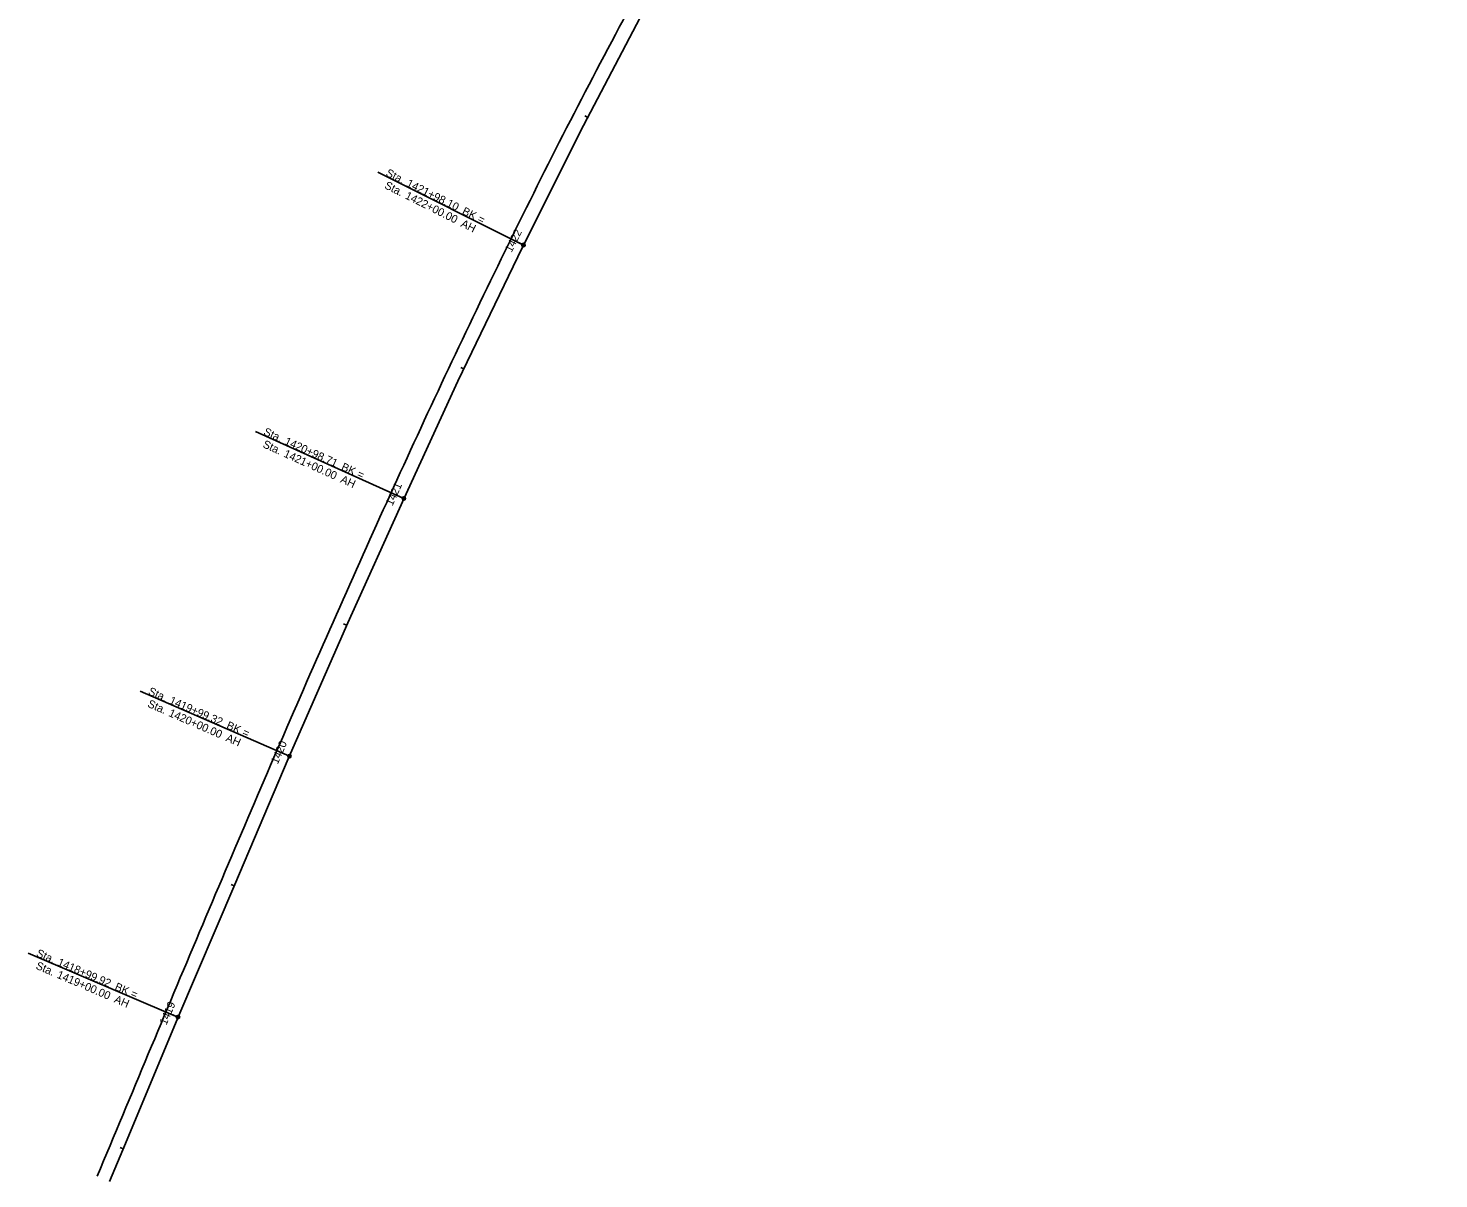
# Model space of a CAD drawing. Extents: x 158351 to 160372, y 373672 to 375743.
# Drawn here: x 158581.7 to 159075.4, y 374197.4 to 374600.1 of the extents above; entities that cross this region are included whole.
import ezdxf

# ---------------------------------------------------------------- set-up
doc = ezdxf.new("R2010")
doc.units = 0
for name, color, linetype in [('Default', 7, 'Continuous'), ('GE_X_Alignment', 7, 'Continuous'), ('GE_X_Alignment_1000_Cardinal_Points', 7, 'Continuous'), ('GE_X_Alignment_1000_Stations', 7, 'Continuous'), ('GE_X_Alignment_100_Cardinal_Points', 7, 'Continuous'), ('GE_X_Alignment_100_Stations', 7, 'Continuous'), ('GE_X_Alignment_500_Cardinal_Points', 7, 'Continuous'), ('GE_X_Alignment_500_Stations', 7, 'Continuous')]:
    doc.layers.add(name, color=color, linetype=linetype)

msp = doc.modelspace()

# ---------------------------------------------------------------- linework, layer by layer
at = {"layer": 'Default'}
msp.add_open_spline([(158605.87, 374198.29), (158611.83, 374212.58), (158623.73, 374241.11), (158641.65, 374283.82), (158659.69, 374326.35), (158677.95, 374368.65), (158696.5, 374410.69), (158715.42, 374452.44), (158734.8, 374493.84), (158754.72, 374534.84), (158775.19, 374575.44), (158789.46, 374602.13), (158796.59, 374615.46)], degree=3, dxfattribs=at)
at = {"layer": 'GE_X_Alignment'}
msp.add_lwpolyline([(158610.16, 374196.5), (158615.74, 374209.73), (158634.02, 374253.79), (158653.96, 374300.37), (158672.72, 374344.4), (158693.52, 374392.04), (158713.24, 374435.64), (158732.12, 374476.57), (158754.66, 374523.45), (158776.04, 374566.09), (158799.53, 374610.86), (158824.66, 374655.89), (158846.86, 374694.4), (158871.75, 374734.35), (158899.56, 374777.58), (158924.58, 374814.76), (158954.14, 374857.23), (158981.31, 374893.58), (159012.91, 374934.64), (159042.19, 374970.87), (159075.38, 375009.78)], dxfattribs=at)
at = {"layer": 'GE_X_Alignment_1000_Cardinal_Points'}
for p, q in [((158755.06, 374524.24), (158704.1, 374549.79)), ((158713.19, 374435.53), (158661.25, 374459.02)), ((158673.13, 374345.32), (158620.88, 374368.12)), ((158634.11, 374253.99), (158581.7, 374276.41))]:
    msp.add_line(p, q, dxfattribs=at)
for centre in [(158755.06, 374524.24), (158713.19, 374435.53), (158673.13, 374345.32), (158634.11, 374253.99)]:
    msp.add_circle(centre, 0.6, dxfattribs=at)
at = {"layer": 'GE_X_Alignment_1000_Stations'}
msp.add_line((158673.13, 374345.32), (158671.29, 374346.12), dxfattribs=at)
at = {"layer": 'GE_X_Alignment_100_Cardinal_Points'}
for p, q in [((158755.06, 374524.24), (158704.1, 374549.79)), ((158713.19, 374435.53), (158661.25, 374459.02)), ((158673.13, 374345.32), (158620.88, 374368.12)), ((158634.11, 374253.99), (158581.7, 374276.41))]:
    msp.add_line(p, q, dxfattribs=at)
for centre in [(158755.06, 374524.24), (158713.19, 374435.53), (158673.13, 374345.32), (158634.11, 374253.99)]:
    msp.add_circle(centre, 0.6, dxfattribs=at)
at = {"layer": 'GE_X_Alignment_100_Stations'}
for p, q in [((158777.52, 374568.91), (158776.46, 374569.47)), ((158755.06, 374524.24), (158753.27, 374525.14)), ((158734.2, 374480.9), (158733.12, 374481.42)), ((158713.19, 374435.53), (158711.36, 374436.35)), ((158693.12, 374391.14), (158692.02, 374391.62)), ((158673.13, 374345.32), (158671.29, 374346.12)), ((158653.78, 374299.95), (158652.68, 374300.43)), ((158634.11, 374253.99), (158632.27, 374254.77)), ((158614.97, 374207.89), (158613.86, 374208.35))]:
    msp.add_line(p, q, dxfattribs=at)
at = {"layer": 'GE_X_Alignment_500_Cardinal_Points'}
for p, q in [((158755.06, 374524.24), (158704.1, 374549.79)), ((158713.19, 374435.53), (158661.25, 374459.02)), ((158673.13, 374345.32), (158620.88, 374368.12)), ((158634.11, 374253.99), (158581.7, 374276.41))]:
    msp.add_line(p, q, dxfattribs=at)
for centre in [(158755.06, 374524.24), (158713.19, 374435.53), (158673.13, 374345.32), (158634.11, 374253.99)]:
    msp.add_circle(centre, 0.6, dxfattribs=at)
at = {"layer": 'GE_X_Alignment_500_Stations'}
for p, q in [((158755.06, 374524.24), (158753.98, 374524.78)), ((158713.19, 374435.53), (158712.09, 374436.02)), ((158673.13, 374345.32), (158671.29, 374346.12)), ((158634.11, 374253.99), (158633, 374254.46))]:
    msp.add_line(p, q, dxfattribs=at)

# ---------------------------------------------------------------- texts
at = {"layer": 'GE_X_Alignment_1000_Cardinal_Points'}
for s, rotation, p in [('Sta. ', 333.3717, (158706.62, 374548.57)), ('Sta. ', 333.3717, (158706.16, 374544.22)), ('1421+98.10', 333.3717, (158713.81, 374544.97)), ('1422+00.00', 333.3717, (158713.36, 374540.62)), (' BK =', 333.3717, (158732.38, 374535.66)), (' AH', 333.3717, (158731.92, 374531.31)), ('Sta. ', 335.6619, (158663.82, 374457.91)), ('Sta. ', 335.6619, (158663.54, 374453.54)), ('1420+98.71', 335.6619, (158671.15, 374454.59)), ('1421+00.00', 335.6619, (158670.86, 374450.23)), (' BK =', 335.6619, (158690.07, 374446.04)), (' AH', 335.6619, (158689.79, 374441.67)), ('Sta. ', 336.4232, (158623.47, 374367.04)), ('Sta. ', 336.4232, (158623.24, 374362.67)), ('1420+00.00', 336.4232, (158630.61, 374359.45)), ('1419+99.32', 336.4232, (158630.84, 374363.82)), (' BK =', 336.4232, (158649.87, 374355.52)), (' AH', 336.4232, (158649.65, 374351.15)), ('Sta. ', 336.8326, (158584.29, 374275.35)), ('Sta. ', 336.8326, (158584.1, 374270.98)), ('1418+99.92', 336.8326, (158591.69, 374272.19)), ('1419+00.00', 336.8326, (158591.49, 374267.82)), (' BK =', 336.8326, (158610.78, 374264.02)), (' AH', 336.8326, (158610.59, 374259.65))]:
    msp.add_text(s, height=2.8, rotation=rotation, dxfattribs=at).set_placement(p)
at = {"layer": 'GE_X_Alignment_1000_Stations'}
msp.add_text('1420', height=2.8, rotation=66.4232, dxfattribs=at).set_placement((158669.04, 374342.33))
at = {"layer": 'GE_X_Alignment_100_Cardinal_Points'}
for s, rotation, p in [('Sta. ', 333.3717, (158706.62, 374548.57)), ('Sta. ', 333.3717, (158706.16, 374544.22)), ('1421+98.10', 333.3717, (158713.81, 374544.97)), ('1422+00.00', 333.3717, (158713.36, 374540.62)), (' BK =', 333.3717, (158732.38, 374535.66)), (' AH', 333.3717, (158731.92, 374531.31)), ('Sta. ', 335.6619, (158663.82, 374457.91)), ('Sta. ', 335.6619, (158663.54, 374453.54)), ('1420+98.71', 335.6619, (158671.15, 374454.59)), ('1421+00.00', 335.6619, (158670.86, 374450.23)), (' BK =', 335.6619, (158690.07, 374446.04)), (' AH', 335.6619, (158689.79, 374441.67)), ('Sta. ', 336.4232, (158623.47, 374367.04)), ('Sta. ', 336.4232, (158623.24, 374362.67)), ('1420+00.00', 336.4232, (158630.61, 374359.45)), ('1419+99.32', 336.4232, (158630.84, 374363.82)), (' BK =', 336.4232, (158649.87, 374355.52)), (' AH', 336.4232, (158649.65, 374351.15)), ('Sta. ', 336.8326, (158584.29, 374275.35)), ('Sta. ', 336.8326, (158584.1, 374270.98)), ('1418+99.92', 336.8326, (158591.69, 374272.19)), ('1419+00.00', 336.8326, (158591.49, 374267.82)), (' BK =', 336.8326, (158610.78, 374264.02)), (' AH', 336.8326, (158610.59, 374259.65))]:
    msp.add_text(s, height=2.8, rotation=rotation, dxfattribs=at).set_placement(p)
at = {"layer": 'GE_X_Alignment_100_Stations'}
for s, rotation, p in [('1422', 63.3717, (158750.87, 374521.46)), ('1421', 65.6619, (158709.18, 374432.73)), ('1420', 66.4232, (158669.04, 374342.33)), ('1419', 66.8326, (158630.06, 374251))]:
    msp.add_text(s, height=2.8, rotation=rotation, dxfattribs=at).set_placement(p)
at = {"layer": 'GE_X_Alignment_500_Cardinal_Points'}
for s, rotation, p in [('Sta. ', 333.3717, (158706.62, 374548.57)), ('Sta. ', 333.3717, (158706.16, 374544.22)), ('1421+98.10', 333.3717, (158713.81, 374544.97)), ('1422+00.00', 333.3717, (158713.36, 374540.62)), (' BK =', 333.3717, (158732.38, 374535.66)), (' AH', 333.3717, (158731.92, 374531.31)), ('Sta. ', 335.6619, (158663.82, 374457.91)), ('Sta. ', 335.6619, (158663.54, 374453.54)), ('1420+98.71', 335.6619, (158671.15, 374454.59)), ('1421+00.00', 335.6619, (158670.86, 374450.23)), (' BK =', 335.6619, (158690.07, 374446.04)), (' AH', 335.6619, (158689.79, 374441.67)), ('Sta. ', 336.4232, (158623.47, 374367.04)), ('Sta. ', 336.4232, (158623.24, 374362.67)), ('1420+00.00', 336.4232, (158630.61, 374359.45)), ('1419+99.32', 336.4232, (158630.84, 374363.82)), (' BK =', 336.4232, (158649.87, 374355.52)), (' AH', 336.4232, (158649.65, 374351.15)), ('Sta. ', 336.8326, (158584.29, 374275.35)), ('Sta. ', 336.8326, (158584.1, 374270.98)), ('1418+99.92', 336.8326, (158591.69, 374272.19)), ('1419+00.00', 336.8326, (158591.49, 374267.82)), (' BK =', 336.8326, (158610.78, 374264.02)), (' AH', 336.8326, (158610.59, 374259.65))]:
    msp.add_text(s, height=2.8, rotation=rotation, dxfattribs=at).set_placement(p)
at = {"layer": 'GE_X_Alignment_500_Stations'}
msp.add_text('1420', height=2.8, rotation=66.4232, dxfattribs=at).set_placement((158669.04, 374342.33))

doc.saveas('drawing.dxf')
